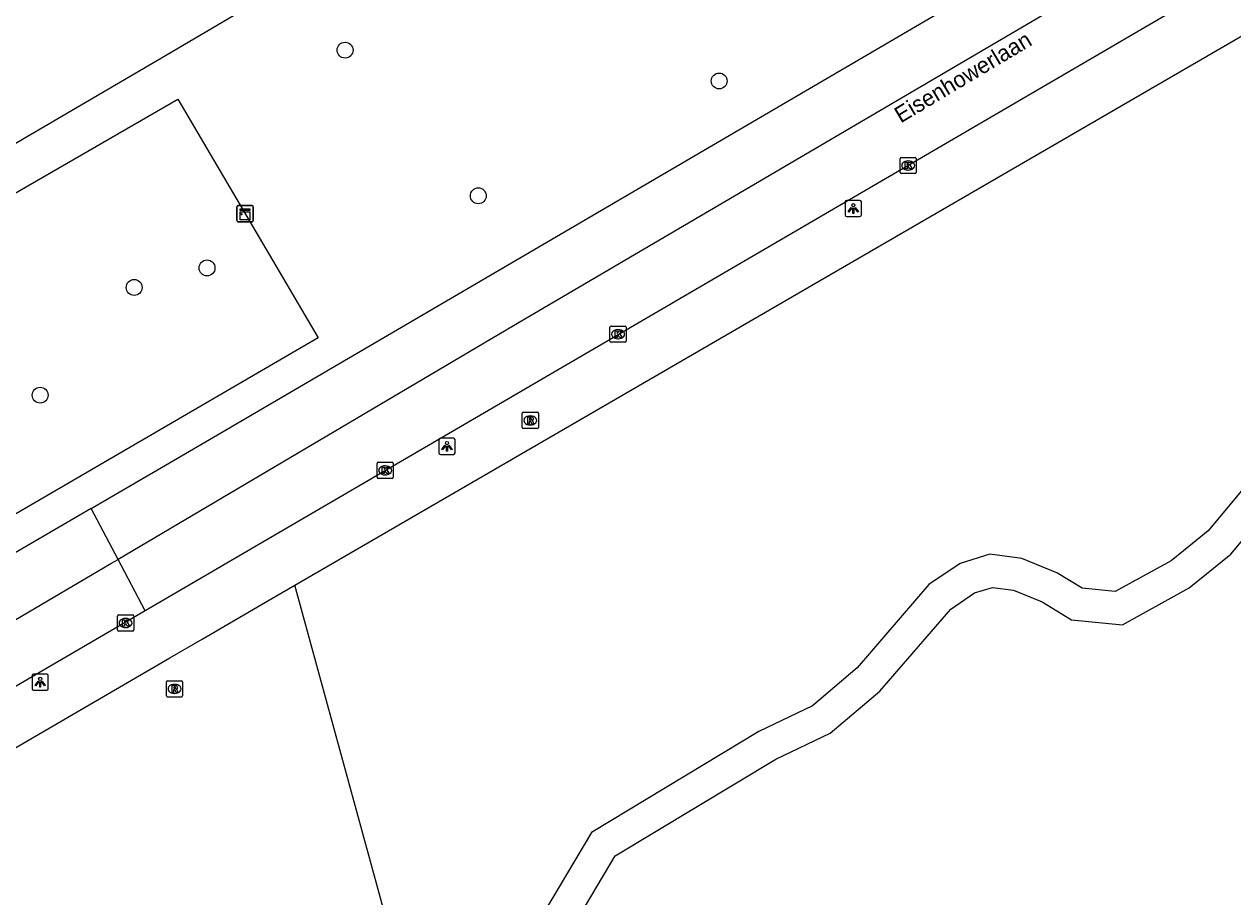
# Model space of a CAD drawing. Extents: x 162880 to 165536, y 384011 to 385179.
# Drawn here: x 163130.7 to 163205.2, y 384332.6 to 384386.3 of the extents above; entities that cross this region are included whole.
import ezdxf

# ---------------------------------------------------------------- set-up
doc = ezdxf.new("R2010")
doc.units = 0
for name, color, linetype in [('IMGEO_Berm_groen', 7, 'Continuous'), ('IMGEO_Boom', 7, 'Continuous'), ('IMGEO_Kast', 7, 'Continuous'), ('IMGEO_Kolk', 7, 'Continuous'), ('IMGEO_Lichtpunt', 7, 'Continuous'), ('IMGEO_Loofbos', 7, 'Continuous'), ('IMGEO_Openbare_ruimte_label', 7, 'Continuous'), ('IMGEO_Rijbaan_regionaal_gesloten', 7, 'Continuous'), ('IMGEO_Rioolput', 7, 'Continuous'), ('IMGEO_Voetpad_onverhard', 7, 'Continuous')]:
    doc.layers.add(name, color=color, linetype=linetype)

msp = doc.modelspace()

# ---------------------------------------------------------------- linework, layer by layer
at = {"layer": 'IMGEO_Berm_groen'}
msp.add_lwpolyline([(163148.842, 384366.976), (163055.696, 384312.747), (162991.211, 384277.349), (162986.763, 384286.167), (162986.414, 384294.29), (162999.918, 384301.631), (163052.601, 384331.084), (163140.211, 384381.691), (163148.842, 384366.976)], dxfattribs=at)
at = {"layer": 'IMGEO_Boom'}
for centre in [(163150.504, 384384.702), (163173.541, 384382.804), (163158.709, 384375.733), (163142.004, 384371.289), (163137.518, 384370.087), (163131.724, 384363.452)]:
    msp.add_circle(centre, 0.489, dxfattribs=at)
at = {"layer": 'IMGEO_Kast'}
for p, q in [((163143.844, 384374.205), (163143.844, 384375.046)), ((163143.844, 384375.046), (163143.844, 384374.205)), ((163143.919, 384375.13), (163144.76, 384375.13)), ((163144.76, 384375.13), (163143.919, 384375.13)), ((163144.844, 384375.055), (163144.844, 384374.214)), ((163144.844, 384374.214), (163144.844, 384375.055)), ((163144.769, 384374.13), (163143.928, 384374.13)), ((163143.928, 384374.13), (163144.769, 384374.13))]:
    msp.add_line(p, q, dxfattribs=at)
for points in [[(163144.039, 384374.92), (163144.639, 384374.92), (163144.639, 384374.835), (163144.039, 384374.835), (163144.039, 384374.92)], [(163144.039, 384374.745), (163144.639, 384374.745), (163144.639, 384374.256), (163144.039, 384374.256), (163144.039, 384374.745)]]:
    msp.add_lwpolyline(points, dxfattribs=at)
msp.add_circle((163144.123, 384374.594), 0.0377, dxfattribs=at)
for centre, start, end in [((163143.922, 384375.052), 92.4484, 184.28452), ((163143.922, 384375.052), 92.4484, 184.28452), ((163144.766, 384375.052), 2.4484, 94.28452), ((163144.766, 384375.052), 2.4484, 94.28452), ((163143.922, 384374.208), 182.4484, 274.28452), ((163143.922, 384374.208), 182.4484, 274.28452), ((163144.766, 384374.208), 272.4484, 4.28452), ((163144.766, 384374.208), 272.4484, 4.28452)]:
    msp.add_arc(centre, 0.0779, start, end, dxfattribs=at)
at = {"layer": 'IMGEO_Kolk'}
for p, q in [((163184.684, 384377.173), (163184.684, 384378.025)), ((163184.759, 384378.099), (163185.611, 384378.099)), ((163185.685, 384378.025), (163185.685, 384377.173)), ((163185.195, 384377.319), (163185.17, 384377.319)), ((163185.172, 384377.879), (163185.197, 384377.879)), ((163185.611, 384377.099), (163184.759, 384377.099)), ((163166.817, 384366.782), (163166.817, 384367.634)), ((163166.892, 384367.708), (163167.744, 384367.708)), ((163167.818, 384367.634), (163167.818, 384366.782)), ((163167.328, 384366.928), (163167.303, 384366.928)), ((163167.305, 384367.488), (163167.33, 384367.488)), ((163167.744, 384366.708), (163166.892, 384366.708)), ((163152.473, 384358.393), (163152.473, 384359.245)), ((163152.548, 384359.319), (163153.4, 384359.319)), ((163152.961, 384359.099), (163152.986, 384359.099)), ((163153.474, 384359.245), (163153.474, 384358.393)), ((163153.4, 384358.319), (163152.548, 384358.319)), ((163152.984, 384358.539), (163152.959, 384358.539)), ((163136.485, 384348.992), (163136.485, 384349.844)), ((163136.56, 384349.918), (163137.412, 384349.918)), ((163136.973, 384349.698), (163136.998, 384349.698)), ((163137.486, 384349.844), (163137.486, 384348.992)), ((163136.996, 384349.138), (163136.971, 384349.138)), ((163137.412, 384348.918), (163136.56, 384348.918))]:
    msp.add_line(p, q, dxfattribs=at)
for points in [[(163184.684, 384377.173), (163184.684, 384378.025)], [(163184.759, 384378.099), (163185.611, 384378.099)], [(163185.685, 384378.025), (163185.685, 384377.173)], [(163185.005, 384377.799), (163185.128, 384377.799), (163185.128, 384377.648), (163185.258, 384377.799), (163185.422, 384377.799), (163185.276, 384377.648), (163185.429, 384377.399), (163185.277, 384377.399), (163185.192, 384377.563), (163185.128, 384377.496), (163185.128, 384377.399), (163185.005, 384377.399), (163185.005, 384377.799)], [(163185.611, 384377.099), (163184.759, 384377.099)], [(163166.817, 384366.782), (163166.817, 384367.634)], [(163166.892, 384367.708), (163167.744, 384367.708)], [(163167.818, 384367.634), (163167.818, 384366.782)], [(163167.138, 384367.408), (163167.261, 384367.408), (163167.261, 384367.257), (163167.391, 384367.408), (163167.555, 384367.408), (163167.409, 384367.257), (163167.562, 384367.008), (163167.41, 384367.008), (163167.325, 384367.172), (163167.261, 384367.105), (163167.261, 384367.008), (163167.138, 384367.008), (163167.138, 384367.408)], [(163167.744, 384366.708), (163166.892, 384366.708)], [(163152.473, 384358.393), (163152.473, 384359.245)], [(163152.548, 384359.319), (163153.4, 384359.319)], [(163152.794, 384359.019), (163152.917, 384359.019), (163152.917, 384358.868), (163153.047, 384359.019), (163153.211, 384359.019), (163153.065, 384358.868), (163153.218, 384358.619), (163153.066, 384358.619), (163152.981, 384358.783), (163152.917, 384358.716), (163152.917, 384358.619), (163152.794, 384358.619), (163152.794, 384359.019)], [(163153.474, 384359.245), (163153.474, 384358.393)], [(163153.4, 384358.319), (163152.548, 384358.319)], [(163136.485, 384348.992), (163136.485, 384349.844)], [(163136.56, 384349.918), (163137.412, 384349.918)], [(163137.486, 384349.844), (163137.486, 384348.992)], [(163136.806, 384349.618), (163136.929, 384349.618), (163136.929, 384349.467), (163137.059, 384349.618), (163137.223, 384349.618), (163137.077, 384349.467), (163137.23, 384349.218), (163137.078, 384349.218), (163136.993, 384349.382), (163136.929, 384349.315), (163136.929, 384349.218), (163136.806, 384349.218), (163136.806, 384349.618)], [(163137.412, 384348.918), (163136.56, 384348.918)]]:
    msp.add_lwpolyline(points, dxfattribs=at)
for centre, start, end in [((163184.761, 384378.023), 91.55205, 178.44795), ((163184.761, 384378.023), 91.55205, 178.44795), ((163185.609, 384378.023), 1.55205, 88.44795), ((163185.609, 384378.023), 1.55205, 88.44795), ((163184.761, 384377.175), 181.55205, 268.44795), ((163184.761, 384377.175), 181.55205, 268.44795), ((163185.609, 384377.175), 271.55205, 358.44795), ((163185.609, 384377.175), 271.55205, 358.44795), ((163166.894, 384367.632), 91.55205, 178.44795), ((163166.894, 384367.632), 91.55205, 178.44795), ((163167.742, 384367.632), 1.55205, 88.44795), ((163167.742, 384367.632), 1.55205, 88.44795), ((163166.894, 384366.784), 181.55205, 268.44795), ((163166.894, 384366.784), 181.55205, 268.44795), ((163167.742, 384366.784), 271.55205, 358.44795), ((163167.742, 384366.784), 271.55205, 358.44795), ((163152.55, 384359.243), 91.55205, 178.44795), ((163152.55, 384359.243), 91.55205, 178.44795), ((163153.398, 384359.243), 1.55205, 88.44795), ((163153.398, 384359.243), 1.55205, 88.44795), ((163152.55, 384358.395), 181.55205, 268.44795), ((163152.55, 384358.395), 181.55205, 268.44795), ((163153.398, 384358.395), 271.55205, 358.44795), ((163153.398, 384358.395), 271.55205, 358.44795), ((163136.562, 384349.842), 91.55205, 178.44795), ((163136.562, 384349.842), 91.55205, 178.44795), ((163137.41, 384349.842), 1.55205, 88.44795), ((163137.41, 384349.842), 1.55205, 88.44795), ((163136.562, 384348.994), 181.55205, 268.44795), ((163136.562, 384348.994), 181.55205, 268.44795), ((163137.41, 384348.994), 271.55205, 358.44795), ((163137.41, 384348.994), 271.55205, 358.44795)]:
    msp.add_arc(centre, 0.0765, start, end, dxfattribs=at)
for centre, major_axis, ratio, start_param, end_param in [((163185.171, 384377.599), (-0.387, 0.002), 0.722429, 4.712389, 7.853982), ((163185.196, 384377.599), (-0.39, 0.002), 0.717154, 1.570796, 4.712389), ((163167.304, 384367.208), (-0.387, 0.002), 0.722429, 4.712389, 7.853982), ((163167.329, 384367.208), (-0.39, 0.002), 0.717154, 1.570796, 4.712389), ((163152.96, 384358.819), (-0.387, 0.002), 0.722429, 4.712389, 7.853982), ((163152.985, 384358.819), (-0.39, 0.002), 0.717154, 1.570796, 4.712389), ((163136.972, 384349.418), (-0.387, 0.002), 0.722429, 4.712389, 7.853982), ((163136.997, 384349.418), (-0.39, 0.002), 0.717154, 1.570796, 4.712389)]:
    msp.add_ellipse(centre, major_axis=major_axis, ratio=ratio, start_param=start_param, end_param=end_param, dxfattribs=at)
at = {"layer": 'IMGEO_Lichtpunt'}
for p, q in [((163181.304, 384375.356), (163181.304, 384374.549)), ((163181.304, 384375.356), (163181.304, 384374.549)), ((163182.206, 384375.451), (163181.398, 384375.451)), ((163182.206, 384375.451), (163181.398, 384375.451)), ((163182.3, 384374.549), (163182.3, 384375.356)), ((163182.3, 384374.549), (163182.3, 384375.356)), ((163181.398, 384374.455), (163182.206, 384374.455)), ((163181.398, 384374.455), (163182.206, 384374.455)), ((163156.28, 384360.702), (163156.28, 384359.895)), ((163156.28, 384360.702), (163156.28, 384359.895)), ((163157.182, 384360.797), (163156.374, 384360.797)), ((163157.182, 384360.797), (163156.374, 384360.797)), ((163157.276, 384359.895), (163157.276, 384360.702)), ((163157.276, 384359.895), (163157.276, 384360.702)), ((163156.374, 384359.801), (163157.182, 384359.801)), ((163156.374, 384359.801), (163157.182, 384359.801)), ((163131.229, 384346.175), (163131.229, 384345.368)), ((163131.229, 384346.175), (163131.229, 384345.368)), ((163132.131, 384346.27), (163131.323, 384346.27)), ((163132.131, 384346.27), (163131.323, 384346.27)), ((163132.225, 384345.368), (163132.225, 384346.175)), ((163132.225, 384345.368), (163132.225, 384346.175)), ((163131.323, 384345.274), (163132.131, 384345.274)), ((163131.323, 384345.274), (163132.131, 384345.274))]:
    msp.add_line(p, q, dxfattribs=at)
for points in [[(163181.678, 384375.02), (163181.717, 384374.992), (163181.529, 384374.73), (163181.491, 384374.757), (163181.678, 384375.02)], [(163181.89, 384374.992), (163181.928, 384375.019), (163182.115, 384374.757), (163182.076, 384374.729), (163181.89, 384374.992)], [(163181.78, 384374.972), (163181.827, 384374.972), (163181.827, 384374.65), (163181.78, 384374.65), (163181.78, 384374.972)], [(163156.654, 384360.366), (163156.693, 384360.338), (163156.505, 384360.076), (163156.467, 384360.103), (163156.654, 384360.366)], [(163156.756, 384360.318), (163156.803, 384360.318), (163156.803, 384359.996), (163156.756, 384359.996), (163156.756, 384360.318)], [(163156.866, 384360.338), (163156.904, 384360.365), (163157.091, 384360.103), (163157.052, 384360.075), (163156.866, 384360.338)], [(163131.603, 384345.839), (163131.642, 384345.811), (163131.454, 384345.549), (163131.416, 384345.576), (163131.603, 384345.839)], [(163131.705, 384345.791), (163131.752, 384345.791), (163131.752, 384345.469), (163131.705, 384345.469), (163131.705, 384345.791)], [(163131.815, 384345.811), (163131.853, 384345.838), (163132.04, 384345.576), (163132.001, 384345.548), (163131.815, 384345.811)]]:
    msp.add_lwpolyline(points, dxfattribs=at)
for centre in [(163181.803, 384375.154), (163156.779, 384360.5), (163131.728, 384345.973)]:
    msp.add_circle(centre, 0.0994, dxfattribs=at)
for centre, start, end in [((163181.398, 384375.356), 90, 180), ((163181.398, 384375.356), 90, 180), ((163182.206, 384375.356), 0, 90), ((163182.206, 384375.356), 0, 90), ((163181.398, 384374.549), 180, 270), ((163181.398, 384374.549), 180, 270), ((163182.206, 384374.549), 270, 0), ((163182.206, 384374.549), 270, 360), ((163156.374, 384360.702), 90, 180), ((163156.374, 384360.702), 90, 180), ((163157.182, 384360.702), 0, 90), ((163157.182, 384360.702), 0, 90), ((163156.374, 384359.895), 180, 270), ((163156.374, 384359.895), 180, 270), ((163157.182, 384359.895), 270, 0), ((163157.182, 384359.895), 270, 360), ((163131.323, 384346.175), 90, 180), ((163131.323, 384346.175), 90, 180), ((163132.131, 384346.175), 0, 90), ((163132.131, 384346.175), 0, 90), ((163131.323, 384345.368), 180, 270), ((163131.323, 384345.368), 180, 270), ((163132.131, 384345.368), 270, 0), ((163132.131, 384345.368), 270, 360)]:
    msp.add_arc(centre, 0.0946, start, end, dxfattribs=at)
at = {"layer": 'IMGEO_Loofbos'}
for points in [[(163147.412, 384351.742), (163229.097, 384399.154), (163272.33, 384424.447), (163305.16, 384443.366), (163305.544, 384443.588)], [(163015.053, 384262.437), (163010.306, 384266.101), (163010.259, 384272.54), (163015.983, 384275.987), (163044.781, 384289.14), (163054.546, 384290.508), (163057.113, 384293.326), (163061.012, 384294.747), (163074.049, 384307.518), (163078.609, 384311.03), (163103.227, 384326.016), (163139.713, 384347.269), (163141.708, 384348.431), (163145.603, 384350.692), (163147.412, 384351.742)], [(163158.27, 384312.081), (163147.412, 384351.742)]]:
    msp.add_lwpolyline(points, dxfattribs=at)
at = {"layer": 'IMGEO_Rijbaan_regionaal_gesloten'}
for points in [[(163124.723, 384375.774), (163138.358, 384383.738), (163138.843, 384384.023), (163211.461, 384426.757), (163256.317, 384453.078), (163273.206, 384463), (163290.991, 384473.343), (163308.788, 384483.676), (163325.692, 384493.499), (163336.884, 384500), (163342.393, 384503.2), (163342.624, 384503.334), (163359.588, 384513.164), (163377.433, 384523.409), (163394.422, 384533.139), (163412.272, 384543.331), (163427.537, 384552.025), (163447.16, 384563.196), (163463.28, 384572.441), (163480.314, 384582.094), (163500, 384593.26)], [(163134.875, 384356.468), (163142.16, 384360.715), (163149.867, 384365.229), (163197.962, 384393.395), (163222.445, 384407.821), (163353.264, 384484.905)], [(163354.963, 384482.045), (163346.799, 384477.262), (163336.414, 384471.12), (163256.03, 384423.663), (163225.608, 384405.722), (163160.883, 384367.724), (163136.524, 384353.333)], [(163356.886, 384478.81), (163202.966, 384387.982), (163138.189, 384350.166)], [(163134.875, 384356.468), (163065.69, 384316.128), (163047.71, 384305.906), (163000, 384279.879), (162992.774, 384275.937), (162992.107, 384275.576), (162958.296, 384257.287)], [(163136.524, 384353.333), (163134.875, 384356.468)], [(162938.038, 384236.628), (162940.823, 384239.608), (162943.802, 384242.49), (162946.914, 384245.082), (162950.166, 384247.581), (162956.166, 384251.683), (162966.682, 384257.842), (162984.518, 384267.432), (163019.119, 384286.121), (163075.431, 384317.808), (163102.908, 384333.537), (163136.085, 384353.074), (163136.524, 384353.333)], [(163138.189, 384350.166), (163136.524, 384353.333)], [(163138.189, 384350.166), (163091.98, 384323.19), (163060.001, 384304.827), (163000, 384271.727), (162995.148, 384269.194), (162989.657, 384266.154), (162987.354, 384264.896)]]:
    msp.add_lwpolyline(points, dxfattribs=at)
at = {"layer": 'IMGEO_Rioolput'}
for p, q in [((163161.411, 384361.47), (163161.411, 384362.322)), ((163161.486, 384362.396), (163162.338, 384362.396)), ((163162.412, 384362.322), (163162.412, 384361.47)), ((163161.922, 384361.616), (163161.897, 384361.616)), ((163161.899, 384362.176), (163161.924, 384362.176)), ((163162.338, 384361.396), (163161.486, 384361.396)), ((163139.499, 384344.934), (163139.499, 384345.786)), ((163139.574, 384345.86), (163140.426, 384345.86)), ((163139.987, 384345.64), (163140.012, 384345.64)), ((163140.5, 384345.786), (163140.5, 384344.934)), ((163140.426, 384344.86), (163139.574, 384344.86)), ((163140.01, 384345.08), (163139.985, 384345.08))]:
    msp.add_line(p, q, dxfattribs=at)
for points in [[(163161.411, 384361.47), (163161.411, 384362.322)], [(163161.486, 384362.396), (163162.338, 384362.396)], [(163162.412, 384362.322), (163162.412, 384361.47)], [(163162, 384362.094), (163161.748, 384362.096), (163161.748, 384361.696)], [(163161.748, 384361.696), (163161.872, 384361.696), (163161.872, 384361.858), (163161.883, 384361.858)], [(163161.926, 384362.015), (163161.872, 384362.015), (163161.872, 384361.934)], [(163161.872, 384361.934), (163161.924, 384361.934)], [(163161.93, 384361.829), (163162.001, 384361.696), (163162.141, 384361.696), (163162.076, 384361.822)], [(163162.338, 384361.396), (163161.486, 384361.396)], [(163139.499, 384344.934), (163139.499, 384345.786)], [(163139.574, 384345.86), (163140.426, 384345.86)], [(163140.088, 384345.558), (163139.836, 384345.56), (163139.836, 384345.16)], [(163139.836, 384345.16), (163139.96, 384345.16), (163139.96, 384345.322), (163139.971, 384345.322)], [(163140.014, 384345.479), (163139.96, 384345.479), (163139.96, 384345.398)], [(163139.96, 384345.398), (163140.012, 384345.398)], [(163140.018, 384345.293), (163140.089, 384345.16), (163140.229, 384345.16), (163140.164, 384345.286)], [(163140.5, 384345.786), (163140.5, 384344.934)], [(163140.426, 384344.86), (163139.574, 384344.86)]]:
    msp.add_lwpolyline(points, dxfattribs=at)
for centre, radius, start, end in [((163161.488, 384362.32), 0.0765, 91.55205, 178.44795), ((163161.488, 384362.32), 0.0765, 91.55205, 178.44795), ((163162.336, 384362.32), 0.0765, 1.55205, 88.44795), ((163162.336, 384362.32), 0.0765, 1.55205, 88.44795), ((163161.882, 384361.805), 0.0533, 26.02933, 88.69889), ((163161.908, 384362.123), 0.19, 274.7715, 282.96867), ((163161.932, 384361.919), 0.0964, 77.00612, 93.18647), ((163161.946, 384361.976), 0.0378, 276.66336, 79.67722), ((163161.999, 384361.984), 0.109, 350.36119, 89.41601), ((163161.997, 384361.984), 0.112, 277.58423, 350.98172), ((163161.981, 384361.769), 0.108, 29.51342, 73.79051), ((163161.488, 384361.472), 0.0765, 181.55205, 268.44795), ((163161.488, 384361.472), 0.0765, 181.55205, 268.44795), ((163162.336, 384361.472), 0.0765, 271.55205, 358.44795), ((163162.336, 384361.472), 0.0765, 271.55205, 358.44795), ((163139.576, 384345.784), 0.0765, 91.55205, 178.44795), ((163139.576, 384345.784), 0.0765, 91.55205, 178.44795), ((163139.97, 384345.269), 0.0533, 26.02933, 88.69889), ((163139.996, 384345.587), 0.19, 274.7715, 282.96867), ((163140.02, 384345.383), 0.0964, 77.00612, 93.18647), ((163140.034, 384345.44), 0.0378, 276.66336, 79.67722), ((163140.087, 384345.448), 0.109, 350.36119, 89.41601), ((163140.085, 384345.448), 0.112, 277.58423, 350.98172), ((163140.069, 384345.233), 0.108, 29.51342, 73.79051), ((163140.424, 384345.784), 0.0765, 1.55205, 88.44795), ((163140.424, 384345.784), 0.0765, 1.55205, 88.44795), ((163139.576, 384344.936), 0.0765, 181.55205, 268.44795), ((163139.576, 384344.936), 0.0765, 181.55205, 268.44795), ((163140.424, 384344.936), 0.0765, 271.55205, 358.44795), ((163140.424, 384344.936), 0.0765, 271.55205, 358.44795)]:
    msp.add_arc(centre, radius, start, end, dxfattribs=at)
for centre, major_axis, ratio, start_param, end_param in [((163161.898, 384361.896), (-0.387, 0.002), 0.722429, 4.712389, 7.853982), ((163161.923, 384361.896), (-0.39, 0.002), 0.717154, 1.570796, 4.712389), ((163139.986, 384345.36), (-0.387, 0.002), 0.722429, 4.712389, 7.853982), ((163140.011, 384345.36), (-0.39, 0.002), 0.717154, 1.570796, 4.712389)]:
    msp.add_ellipse(centre, major_axis=major_axis, ratio=ratio, start_param=start_param, end_param=end_param, dxfattribs=at)
at = {"layer": 'IMGEO_Voetpad_onverhard'}
for points in [[(163207.856, 384360.119), (163203.656, 384355.092), (163201.376, 384353.257), (163197.94, 384351.366), (163195.894, 384351.559), (163194.341, 384352.514), (163192.179, 384353.396), (163190.215, 384353.652), (163188.392, 384353.092), (163186.463, 384351.781), (163182.035, 384346.651), (163179.291, 384344.325), (163175.991, 384342.737), (163165.672, 384336.523), (163160.73, 384328.191), (163159.169, 384324.318), (163160.013, 384319.249), (163162.156, 384313.029)], [(163164.107, 384313.505), (163161.959, 384319.742), (163161.234, 384324.092), (163162.528, 384327.302), (163167.135, 384335.069), (163177.023, 384341.024), (163180.387, 384342.633), (163183.442, 384345.222), (163187.81, 384350.278), (163189.268, 384351.268), (163190.387, 384351.613), (163191.664, 384351.446), (163193.434, 384350.724), (163195.243, 384349.611), (163198.379, 384349.316), (163202.49, 384351.586), (163205.064, 384353.658), (163209.662, 384359.161)]]:
    msp.add_lwpolyline(points, dxfattribs=at)

# ---------------------------------------------------------------- texts
at = {"layer": 'IMGEO_Openbare_ruimte_label'}
msp.add_text('Eisenhowerlaan', height=1, rotation=30.79671, dxfattribs=at).set_placement((163184.723, 384380.182))

doc.saveas('drawing.dxf')
